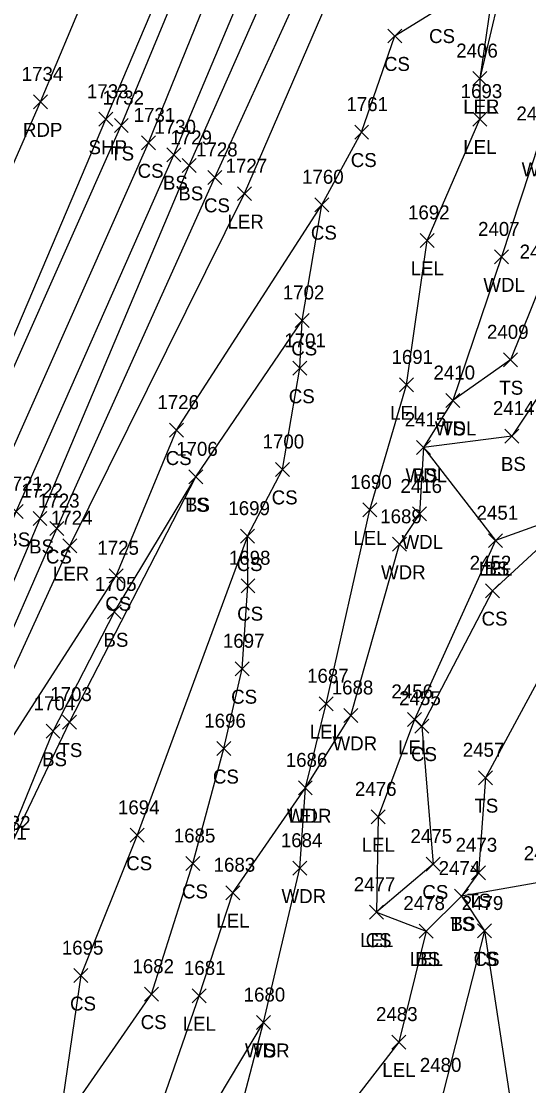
# Model space of a CAD drawing. Extents: x 1483143 to 1488182, y 802902 to 807581.
# Drawn here: x 1487754.7 to 1487827.4, y 806100.3 to 806252.6 of the extents above; entities that cross this region are included whole.
import ezdxf

# ---------------------------------------------------------------- set-up
doc = ezdxf.new("R2010")
doc.units = 0
for name, color, linetype in [('L_A', 7, 'Continuous'), ('L_I', 7, 'Continuous'), ('L_TIC', 7, 'Continuous'), ('LARO', 7, 'Continuous'), ('LAWA', 7, 'Continuous'), ('LELB', 7, 'Continuous'), ('P_A', 7, 'Continuous'), ('P_I', 7, 'Continuous'), ('P_TIC', 7, 'Continuous'), ('PET', 7, 'Continuous'), ('PSP', 7, 'Continuous')]:
    doc.layers.add(name, color=color, linetype=linetype)

msp = doc.modelspace()

# ---------------------------------------------------------------- linework, layer by layer
at = {"layer": 'L_TIC'}
for points in [[(1487807.19, 806249.46), (1487809.19, 806251.46)], [(1487809.19, 806249.46), (1487807.19, 806251.46)], [(1487819.37, 806243.37), (1487821.37, 806245.37)], [(1487821.37, 806243.37), (1487819.37, 806245.37)], [(1487819.37, 806243.37), (1487821.37, 806245.37)], [(1487821.37, 806243.37), (1487819.37, 806245.37)], [(1487819.35, 806237.57), (1487821.35, 806239.57)], [(1487821.35, 806237.57), (1487819.35, 806239.57)], [(1487768.04, 806236.65), (1487770.04, 806238.65)], [(1487770.04, 806236.65), (1487768.04, 806238.65)], [(1487802.44, 806235.71), (1487804.44, 806237.71)], [(1487804.44, 806235.71), (1487802.44, 806237.71)], [(1487771.93, 806234.17), (1487773.93, 806236.17)], [(1487773.93, 806234.17), (1487771.93, 806236.17)], [(1487775.55, 806232.47), (1487777.55, 806234.47)], [(1487777.55, 806232.47), (1487775.55, 806234.47)], [(1487777.76, 806230.94), (1487779.76, 806232.94)], [(1487779.76, 806230.94), (1487777.76, 806232.94)], [(1487781.43, 806229.23), (1487783.43, 806231.23)], [(1487783.43, 806229.23), (1487781.43, 806231.23)], [(1487785.65, 806226.9), (1487787.65, 806228.9)], [(1487787.65, 806226.9), (1487785.65, 806228.9)], [(1487796.73, 806225.32), (1487798.73, 806227.32)], [(1487798.73, 806225.32), (1487796.73, 806227.32)], [(1487796.73, 806225.32), (1487798.73, 806227.32)], [(1487798.73, 806225.32), (1487796.73, 806227.32)], [(1487811.82, 806220.22), (1487813.82, 806222.22)], [(1487813.82, 806220.22), (1487811.82, 806222.22)], [(1487822.44, 806217.85), (1487824.44, 806219.85)], [(1487824.44, 806217.85), (1487822.44, 806219.85)], [(1487793.92, 806208.76), (1487795.92, 806210.76)], [(1487795.92, 806208.76), (1487793.92, 806210.76)], [(1487823.73, 806203.13), (1487825.73, 806205.13)], [(1487825.73, 806203.13), (1487823.73, 806205.13)], [(1487793.57, 806201.91), (1487795.57, 806203.91)], [(1487795.57, 806201.91), (1487793.57, 806203.91)], [(1487808.88, 806199.54), (1487810.88, 806201.54)], [(1487810.88, 806199.54), (1487808.88, 806201.54)], [(1487815.5, 806197.3), (1487817.5, 806199.3)], [(1487817.5, 806197.3), (1487815.5, 806199.3)], [(1487815.5, 806197.3), (1487817.5, 806199.3)], [(1487817.5, 806197.3), (1487815.5, 806199.3)], [(1487775.95, 806193.07), (1487777.95, 806195.07)], [(1487777.95, 806193.07), (1487775.95, 806195.07)], [(1487823.92, 806192.22), (1487825.92, 806194.22)], [(1487825.92, 806192.22), (1487823.92, 806194.22)], [(1487811.31, 806190.59), (1487813.31, 806192.59)], [(1487813.31, 806190.59), (1487811.31, 806192.59)], [(1487811.31, 806190.59), (1487813.31, 806192.59)], [(1487813.31, 806190.59), (1487811.31, 806192.59)], [(1487791.12, 806187.44), (1487793.12, 806189.44)], [(1487793.12, 806187.44), (1487791.12, 806189.44)], [(1487778.72, 806186.39), (1487780.72, 806188.39)], [(1487780.72, 806186.39), (1487778.72, 806188.39)], [(1487778.72, 806186.39), (1487780.72, 806188.39)], [(1487780.72, 806186.39), (1487778.72, 806188.39)], [(1487753, 806181.42), (1487755, 806183.42)], [(1487755, 806181.42), (1487753, 806183.42)], [(1487803.62, 806181.65), (1487805.62, 806183.65)], [(1487805.62, 806181.65), (1487803.62, 806183.65)], [(1487810.73, 806181.07), (1487812.73, 806183.07)], [(1487812.73, 806181.07), (1487810.73, 806183.07)], [(1487756.4, 806180.42), (1487758.4, 806182.42)], [(1487758.4, 806180.42), (1487756.4, 806182.42)], [(1487758.8, 806178.98), (1487760.8, 806180.98)], [(1487760.8, 806178.98), (1487758.8, 806180.98)], [(1487786.1, 806177.9), (1487788.1, 806179.9)], [(1487788.1, 806177.9), (1487786.1, 806179.9)], [(1487760.66, 806176.53), (1487762.66, 806178.53)], [(1487762.66, 806176.53), (1487760.66, 806178.53)], [(1487807.85, 806176.73), (1487809.85, 806178.73)], [(1487809.85, 806176.73), (1487807.85, 806178.73)], [(1487821.58, 806177.25), (1487823.58, 806179.25)], [(1487823.58, 806177.25), (1487821.58, 806179.25)], [(1487821.58, 806177.25), (1487823.58, 806179.25)], [(1487823.58, 806177.25), (1487821.58, 806179.25)], [(1487767.3, 806172.23), (1487769.3, 806174.23)], [(1487769.3, 806172.23), (1487767.3, 806174.23)], [(1487786.17, 806170.8), (1487788.17, 806172.8)], [(1487788.17, 806170.8), (1487786.17, 806172.8)], [(1487821.16, 806170.09), (1487823.16, 806172.09)], [(1487823.16, 806170.09), (1487821.16, 806172.09)], [(1487767.04, 806167.06), (1487769.04, 806169.06)], [(1487769.04, 806167.06), (1487767.04, 806169.06)], [(1487785.32, 806158.92), (1487787.32, 806160.92)], [(1487787.32, 806158.92), (1487785.32, 806160.92)], [(1487797.38, 806153.92), (1487799.38, 806155.92)], [(1487799.38, 806153.92), (1487797.38, 806155.92)], [(1487800.9, 806152.24), (1487802.9, 806154.24)], [(1487802.9, 806152.24), (1487800.9, 806154.24)], [(1487760.63, 806151.29), (1487762.63, 806153.29)], [(1487762.63, 806151.29), (1487760.63, 806153.29)], [(1487810.01, 806151.68), (1487812.01, 806153.68)], [(1487812.01, 806151.68), (1487810.01, 806153.68)], [(1487811.07, 806150.71), (1487813.07, 806152.71)], [(1487813.07, 806150.71), (1487811.07, 806152.71)], [(1487758.26, 806149.98), (1487760.26, 806151.98)], [(1487760.26, 806149.98), (1487758.26, 806151.98)], [(1487782.71, 806147.49), (1487784.71, 806149.49)], [(1487784.71, 806147.49), (1487782.71, 806149.49)], [(1487820.17, 806143.33), (1487822.17, 806145.33)], [(1487822.17, 806143.33), (1487820.17, 806145.33)], [(1487794.38, 806141.88), (1487796.38, 806143.88)], [(1487796.38, 806141.88), (1487794.38, 806143.88)], [(1487794.38, 806141.88), (1487796.38, 806143.88)], [(1487796.38, 806141.88), (1487794.38, 806143.88)], [(1487804.8, 806137.73), (1487806.8, 806139.73)], [(1487806.8, 806137.73), (1487804.8, 806139.73)], [(1487770.3, 806135.09), (1487772.3, 806137.09)], [(1487772.3, 806135.09), (1487770.3, 806137.09)], [(1487778.29, 806131.06), (1487780.29, 806133.06)], [(1487780.29, 806131.06), (1487778.29, 806133.06)], [(1487812.69, 806130.97), (1487814.69, 806132.97)], [(1487814.69, 806130.97), (1487812.69, 806132.97)], [(1487793.61, 806130.39), (1487795.61, 806132.39)], [(1487795.61, 806130.39), (1487793.61, 806132.39)], [(1487819.15, 806129.73), (1487821.15, 806131.73)], [(1487821.15, 806129.73), (1487819.15, 806131.73)], [(1487783.99, 806126.88), (1487785.99, 806128.88)], [(1487785.99, 806126.88), (1487783.99, 806128.88)], [(1487816.72, 806126.4), (1487818.72, 806128.4)], [(1487818.72, 806126.4), (1487816.72, 806128.4)], [(1487816.72, 806126.4), (1487818.72, 806128.4)], [(1487818.72, 806126.4), (1487816.72, 806128.4)], [(1487804.57, 806124.09), (1487806.57, 806126.09)], [(1487806.57, 806124.09), (1487804.57, 806126.09)], [(1487804.57, 806124.09), (1487806.57, 806126.09)], [(1487806.57, 806124.09), (1487804.57, 806126.09)], [(1487811.67, 806121.39), (1487813.67, 806123.39)], [(1487813.67, 806121.39), (1487811.67, 806123.39)], [(1487811.67, 806121.39), (1487813.67, 806123.39)], [(1487813.67, 806121.39), (1487811.67, 806123.39)], [(1487820.03, 806121.4), (1487822.03, 806123.4)], [(1487822.03, 806121.4), (1487820.03, 806123.4)], [(1487820.03, 806121.4), (1487822.03, 806123.4)], [(1487822.03, 806121.4), (1487820.03, 806123.4)], [(1487762.26, 806115.01), (1487764.26, 806117.01)], [(1487764.26, 806115.01), (1487762.26, 806117.01)], [(1487772.37, 806112.36), (1487774.37, 806114.36)], [(1487774.37, 806112.36), (1487772.37, 806114.36)], [(1487779.18, 806112.12), (1487781.18, 806114.12)], [(1487781.18, 806112.12), (1487779.18, 806114.12)], [(1487788.38, 806108.3), (1487790.38, 806110.3)], [(1487790.38, 806108.3), (1487788.38, 806110.3)], [(1487788.38, 806108.3), (1487790.38, 806110.3)], [(1487790.38, 806108.3), (1487788.38, 806110.3)], [(1487807.76, 806105.51), (1487809.76, 806107.51)], [(1487809.76, 806105.51), (1487807.76, 806107.51)]]:
    msp.add_lwpolyline(points, dxfattribs=at)
at = {"layer": 'LARO'}
for points in [[(1487666.95, 805964.97), (1487680.31, 805984.75), (1487702.99, 806037.2), (1487715.7, 806058.03), (1487734.3, 806108.53), (1487742.02, 806134.63), (1487761.66, 806177.53), (1487786.65, 806227.9), (1487808.03, 806277.33), (1487813.76, 806294.17), (1487828.9, 806329), (1487831.91, 806346.68), (1487843.29, 806372.21), (1487845.69, 806380.48), (1487852.63, 806386.9), (1487863.18, 806416.3)], [(1487938.33, 806405.75), (1487927.08, 806402.62), (1487919.67, 806403.09), (1487914.11, 806409.79), (1487906.78, 806399.47), (1487893.33, 806381.44), (1487887.6, 806370.68), (1487880.83, 806355.03), (1487873.24, 806335.95), (1487862.81, 806310.84), (1487845.31, 806291.53), (1487837.06, 806275.13), (1487830.31, 806264.75), (1487822.51, 806259.14), (1487820.37, 806244.37)], [(1487865.1, 806267.91), (1487857.3, 806269.9), (1487840.52, 806269.33), (1487830.31, 806264.75), (1487823.62, 806258.16), (1487820.37, 806244.37)], [(1487820.37, 806244.37), (1487820.35, 806238.57)], [(1487707.45, 805965.6), (1487711.43, 805989.94), (1487729.08, 806015.73), (1487727.61, 806022.94), (1487733.3, 806030.69), (1487757.71, 806067.53), (1487771.86, 806089.23), (1487780.18, 806113.12), (1487784.99, 806127.88), (1487795.38, 806142.88), (1487798.38, 806154.92), (1487804.62, 806182.65), (1487809.88, 806200.54), (1487812.82, 806221.22), (1487820.35, 806238.57)], [(1487840.18, 806185.42), (1487834.67, 806182.6), (1487822.58, 806178.25), (1487811.01, 806152.68), (1487805.8, 806138.73), (1487805.57, 806125.09), (1487812.67, 806122.39), (1487808.76, 806106.51), (1487799.94, 806095.08), (1487791.75, 806069.31), (1487789.16, 806039.67), (1487787.77, 806021.85), (1487782.39, 806010.38), (1487772.44, 806000.5), (1487764.14, 805988.07), (1487767.26, 805965.45), (1487766, 805943.66), (1487763.65, 805933.94), (1487758.69, 805910.3), (1487765.4, 805900.12), (1487775.65, 805902.89)]]:
    msp.add_lwpolyline(points, dxfattribs=at)
at = {"layer": 'LAWA'}
for points in [[(1487942.37, 806424.18), (1487942.13, 806400.96), (1487924.66, 806393.36), (1487906.74, 806373.16), (1487899.59, 806370.18), (1487890.83, 806350.54), (1487893.79, 806329.46), (1487876.29, 806319.09), (1487863.09, 806294.65), (1487840.52, 806269.33), (1487843.55, 806264.22), (1487833.59, 806259.9), (1487830.72, 806250.51), (1487828.92, 806235.37), (1487823.44, 806218.85), (1487816.5, 806198.3), (1487812.31, 806191.59), (1487811.73, 806182.07)], [(1487811.73, 806182.07), (1487808.85, 806177.73)], [(1487715.74, 805966.94), (1487726.15, 805982.46), (1487744.09, 806004.51), (1487749.42, 806025.91), (1487761.62, 806062.94), (1487776.28, 806087.32), (1487789.38, 806109.3), (1487794.61, 806131.39), (1487795.38, 806142.88), (1487801.9, 806153.24), (1487808.85, 806177.73)]]:
    msp.add_lwpolyline(points, dxfattribs=at)
at = {"layer": 'LELB'}
for points in [[(1487406.66, 805485.41), (1487431.45, 805531.24), (1487454.84, 805575.74), (1487473.75, 805612.05), (1487489.43, 805642.37), (1487507.64, 805678.53), (1487524.82, 805711.39), (1487541.86, 805746.09), (1487557.67, 805776.44), (1487575.49, 805812.01), (1487597.52, 805857.93), (1487620.62, 805906.82), (1487641.85, 805951.94), (1487662.18, 805996.35), (1487684.09, 806043.93), (1487694.42, 806066.95), (1487726.58, 806140.7), (1487745.85, 806185.55), (1487769.04, 806237.65), (1487788.58, 806284.85), (1487808.3, 806333.26), (1487827.52, 806379.6), (1487850.09, 806437.73)], [(1487410.04, 805483.24), (1487436.07, 805529.53), (1487459.78, 805575.03), (1487477.42, 805609.67), (1487492.45, 805639.09), (1487509.86, 805677.27), (1487528.68, 805708.85), (1487545.3, 805744.17), (1487561.79, 805774.32), (1487579.7, 805810.21), (1487602.04, 805856.31), (1487624.97, 805905.57), (1487645.72, 805950.02), (1487667.21, 805993.1), (1487687.16, 806043.23), (1487699.2, 806065.16), (1487730.65, 806138.87), (1487749.96, 806183.58), (1487772.93, 806235.17), (1487792.36, 806283.08), (1487812.9, 806331.5), (1487831.61, 806378.23), (1487855.61, 806436.65)], [(1487413.83, 805481.53), (1487440.22, 805526.89), (1487464.36, 805572.85), (1487481.71, 805606.55), (1487496.63, 805636.25), (1487514.9, 805673.97), (1487535.8, 805705.94), (1487549.07, 805741.59), (1487566.17, 805772.22), (1487583.99, 805807.69), (1487605.26, 805855.28), (1487629.33, 805903.01), (1487650.26, 805948.76), (1487670.48, 805991.25), (1487690.28, 806041.74), (1487702.22, 806061.37), (1487704.47, 806066.39), (1487735.28, 806136.71), (1487754, 806182.42), (1487776.55, 806233.47), (1487796.75, 806281.41), (1487816.88, 806330.25), (1487835.19, 806376.59), (1487859.78, 806434.97)], [(1487417, 805480.8), (1487442.28, 805525.8), (1487466.47, 805571.82), (1487483.84, 805604.86), (1487498.25, 805635.76), (1487518.24, 805671.86), (1487538.47, 805704.77), (1487552.2, 805739.67), (1487568.17, 805771.84), (1487585.97, 805806.76), (1487609.39, 805853.47), (1487632.34, 805900.81), (1487653.02, 805947.32), (1487672.59, 805990.01), (1487694.92, 806039.27), (1487707.45, 806059.25), (1487710.05, 806064.3), (1487737.97, 806135.43), (1487757.4, 806181.42), (1487778.76, 806231.94), (1487799.97, 806279.97), (1487818.92, 806329.91), (1487837.5, 806376), (1487863.45, 806433.38)], [(1487539.8, 805706.7), (1487554.99, 805738.51), (1487564.78, 805761.24), (1487572.42, 805770.06), (1487590.42, 805804.18), (1487613.31, 805851.36), (1487639.64, 805896.3), (1487657.07, 805945.9), (1487666.95, 805964.97), (1487675.89, 805987.99), (1487698.82, 806037.9), (1487713.56, 806059.8), (1487740.03, 806134.78), (1487759.8, 806179.98), (1487782.43, 806230.23), (1487804.48, 806278.55), (1487821.45, 806329.34), (1487839.66, 806374.66), (1487865.87, 806433.14)], [(1487757.71, 806067.53), (1487760.04, 806094.14), (1487773.37, 806113.36), (1487779.29, 806132.06), (1487783.71, 806148.49), (1487786.32, 806159.92), (1487787.17, 806171.8), (1487787.1, 806178.9), (1487792.12, 806188.44), (1487794.57, 806202.91), (1487794.92, 806209.76), (1487797.73, 806226.32), (1487803.44, 806236.71), (1487808.19, 806250.46), (1487814.65, 806254.45)], [(1487839.79, 806229.5), (1487829.39, 806215.61), (1487824.73, 806204.13), (1487816.5, 806198.3)], [(1487734.3, 806108.53), (1487743.5, 806131.6), (1487748.42, 806142.35), (1487768.3, 806173.23), (1487776.95, 806194.07), (1487797.73, 806226.32)], [(1487842.83, 806226.01), (1487836.38, 806210.42), (1487824.92, 806193.22), (1487812.31, 806191.59), (1487822.58, 806178.25)], [(1487847.14, 806223.2), (1487840.13, 806209.19), (1487831.79, 806197.78), (1487834.67, 806182.6), (1487832.99, 806166.2), (1487821.17, 806144.33), (1487820.15, 806130.73), (1487817.72, 806127.4), (1487821.03, 806122.4), (1487825.17, 806095.15), (1487826.04, 806071.21), (1487819.68, 806058.95), (1487818.7, 806047.19), (1487815.48, 806048.93), (1487807.41, 806062.56), (1487796.67, 806073.08)], [(1487779.72, 806187.39), (1487794.92, 806209.76)], [(1487709.5, 806045.03), (1487721.98, 806050.95), (1487727.79, 806058.8), (1487736.06, 806080.69), (1487739.04, 806093.16), (1487735.83, 806103.47), (1487734.3, 806108.53), (1487746.67, 806125.92), (1487751.73, 806132.48), (1487759.26, 806150.98), (1487768.04, 806168.06), (1487779.72, 806187.39)], [(1487709.97, 806043.56), (1487721.56, 806049.74), (1487727.77, 806058.21), (1487737.69, 806079.55), (1487741.2, 806090.9), (1487742.36, 806105.05), (1487748.14, 806123.84), (1487752.84, 806133.86), (1487761.63, 806152.29), (1487779.72, 806187.39)], [(1487834.67, 806182.6), (1487822.16, 806171.09), (1487812.07, 806151.71), (1487813.69, 806131.97), (1487805.57, 806125.09)], [(1487787.1, 806178.9), (1487771.3, 806136.09)], [(1487771.3, 806136.09), (1487763.26, 806116.01)], [(1487829.9, 806129.52), (1487817.72, 806127.4), (1487812.67, 806122.39)], [(1487821.03, 806122.4), (1487815.12, 806099.24), (1487803.16, 806087.01), (1487796.67, 806073.08)], [(1487763.26, 806116.01), (1487760.04, 806094.14)], [(1487722.85, 805947.47), (1487728.92, 805957.98), (1487741.86, 805972.44), (1487759.45, 805985.51), (1487774.65, 806014.13), (1487785.01, 806040.02), (1487783.16, 806085.43), (1487789.38, 806109.3)]]:
    msp.add_lwpolyline(points, dxfattribs=at)
at = {"layer": 'P_TIC'}
for points in [[(1487756.48, 806240.03), (1487758.48, 806242.03)], [(1487758.48, 806240.03), (1487756.48, 806242.03)], [(1487765.81, 806237.55), (1487767.81, 806239.55)], [(1487767.81, 806237.55), (1487765.81, 806239.55)]]:
    msp.add_lwpolyline(points, dxfattribs=at)
at = {"layer": 'PET'}
msp.add_lwpolyline([(1487396.33, 805490.41), (1487421.9, 805537.94), (1487444.13, 805580.16), (1487464.29, 805618.83), (1487479.8, 805648.39), (1487498.08, 805684.27), (1487514.57, 805717.15), (1487530.55, 805749.06), (1487547.16, 805782.47), (1487564.33, 805817.54), (1487585.71, 805863.32), (1487608.89, 805911.38), (1487630.35, 805956.68), (1487651.22, 806001.25), (1487672.63, 806048.33), (1487683.65, 806072.29), (1487715.61, 806144.47), (1487735.35, 806190.47), (1487757.48, 806241.03), (1487777.65, 806289.15), (1487798.25, 806337.46), (1487817.05, 806384.04), (1487839.67, 806441.4)], dxfattribs=at)
at = {"layer": 'PSP'}
msp.add_lwpolyline([(1487405.03, 805486.21), (1487429.8, 805532.42), (1487452.92, 805576.31), (1487472.37, 805613.24), (1487487.86, 805643.29), (1487506.35, 805679.4), (1487523.34, 805712.45), (1487540.38, 805746.64), (1487556.03, 805777.85), (1487573.44, 805813.27), (1487595.34, 805859.04), (1487618.37, 805906.67), (1487640.09, 805952.42), (1487660.18, 805997.21), (1487682.38, 806044.71), (1487693.04, 806068.56), (1487725.12, 806141.19), (1487744.39, 806185.87), (1487766.81, 806238.55), (1487786.8, 806285.64), (1487806.77, 806333.93), (1487825.55, 806380.21), (1487847.81, 806437.56)], dxfattribs=at)

# ---------------------------------------------------------------- texts
at = {"layer": 'L_A'}
for s, p in [('CS', (1487813.09, 806249.45)), ('CS', (1487806.63, 806245.46)), ('LER', (1487817.95, 806239.37)), ('LEL', (1487818.01, 806239.37)), ('TS', (1487767.45, 806232.65)), ('LEL', (1487817.98, 806233.57)), ('CS', (1487801.88, 806231.71)), ('CS', (1487771.37, 806230.17)), ('WDL', (1487826.34, 806230.37)), ('BS', (1487774.99, 806228.47)), ('BS', (1487777.2, 806226.94)), ('CS', (1487780.87, 806225.23)), ('LER', (1487784.23, 806222.9)), ('CS', (1487796.17, 806221.32)), ('CS', (1487796.17, 806221.32)), ('LEL', (1487810.46, 806216.22)), ('WDL', (1487820.86, 806213.85)), ('CS', (1487793.36, 806204.76)), ('TS', (1487823.14, 806199.13)), ('CS', (1487793.01, 806197.91)), ('LEL', (1487807.52, 806195.54)), ('WDL', (1487813.92, 806193.3)), ('TS', (1487814.91, 806193.3)), ('CS', (1487775.39, 806189.07)), ('BS', (1487823.37, 806188.22)), ('WDL', (1487809.72, 806186.59)), ('BS', (1487810.75, 806186.59)), ('TS', (1487778.13, 806182.39)), ('BS', (1487778.16, 806182.39)), ('CS', (1487790.56, 806183.44)), ('BS', (1487752.44, 806177.42)), ('BS', (1487755.84, 806176.42)), ('LEL', (1487802.25, 806177.65)), ('WDL', (1487809.15, 806177.07)), ('CS', (1487758.24, 806174.98)), ('CS', (1487785.54, 806173.9)), ('LEL', (1487820.22, 806173.25)), ('BS', (1487821.02, 806173.25)), ('LER', (1487759.24, 806172.53)), ('WDR', (1487806.21, 806172.73)), ('CS', (1487766.74, 806168.23)), ('CS', (1487785.62, 806166.8)), ('CS', (1487820.6, 806166.09)), ('BS', (1487766.48, 806163.06)), ('CS', (1487784.76, 806154.92)), ('LEL', (1487796.01, 806149.92)), ('TS', (1487760.04, 806147.29)), ('WDR', (1487799.27, 806148.24)), ('LEL', (1487808.65, 806147.68)), ('BS', (1487757.7, 806145.98)), ('CS', (1487810.51, 806146.71)), ('CS', (1487782.15, 806143.49)), ('TS', (1487819.58, 806139.33)), ('WDR', (1487792.74, 806137.88)), ('LEL', (1487793.01, 806137.88)), ('LEL', (1487803.44, 806133.73)), ('CS', (1487769.74, 806131.09)), ('CS', (1487777.73, 806127.06)), ('WDR', (1487791.97, 806126.39)), ('CS', (1487812.13, 806126.97)), ('TS', (1487818.56, 806125.73)), ('LEL', (1487782.63, 806122.88)), ('TS', (1487816.13, 806122.4)), ('BS', (1487816.16, 806122.4)), ('LEL', (1487803.21, 806120.09)), ('CS', (1487804.01, 806120.09)), ('LEL', (1487810.31, 806117.39)), ('BS', (1487811.11, 806117.39)), ('TS', (1487819.44, 806117.4)), ('CS', (1487819.47, 806117.4)), ('CS', (1487761.7, 806111.01)), ('CS', (1487771.81, 806108.36)), ('LEL', (1487777.82, 806108.12)), ('WDR', (1487786.74, 806104.3)), ('TS', (1487787.78, 806104.3)), ('LEL', (1487806.39, 806101.51))]:
    msp.add_text(s, height=2, dxfattribs=at).set_placement(p)
at = {"layer": 'L_I'}
for s, p in [('2406', (1487816.98, 806247.37)), ('2406', (1487816.98, 806247.37)), ('1732', (1487766.34, 806240.65)), ('1693', (1487817.61, 806241.57)), ('1761', (1487801.26, 806239.71)), ('1731', (1487770.81, 806238.17)), ('2405', (1487825.59, 806238.37)), ('2405', (1487825.59, 806238.37)), ('1730', (1487773.77, 806236.47)), ('1729', (1487776.06, 806234.94)), ('1728', (1487779.74, 806233.23)), ('1727', (1487783.96, 806230.9)), ('1760', (1487794.91, 806229.32)), ('1760', (1487794.91, 806229.32)), ('1692', (1487810.08, 806224.22)), ('2407', (1487820.1, 806221.85)), ('2408', (1487826.05, 806218.61)), ('1702', (1487792.15, 806212.76)), ('2409', (1487821.38, 806207.13)), ('1701', (1487792.36, 806205.91)), ('1691', (1487807.71, 806203.54)), ('2410', (1487813.72, 806201.3)), ('2410', (1487813.72, 806201.3)), ('1726', (1487774.2, 806197.07)), ('2414', (1487822.23, 806196.22)), ('2415', (1487809.61, 806194.59)), ('2415', (1487809.61, 806194.59)), ('1700', (1487789.26, 806191.44)), ('1706', (1487776.89, 806190.39)), ('1706', (1487776.89, 806190.39)), ('1721', (1487751.88, 806185.42)), ('1690', (1487801.79, 806185.65)), ('1722', (1487754.71, 806184.42)), ('2416', (1487808.99, 806185.07)), ('1723', (1487757.11, 806182.98)), ('1699', (1487784.36, 806181.9)), ('2451', (1487819.89, 806181.25)), ('2451', (1487819.89, 806181.25)), ('1724', (1487758.96, 806180.53)), ('1689', (1487806.1, 806180.73)), ('1725', (1487765.61, 806176.23)), ('1698', (1487784.43, 806174.8)), ('2452', (1487818.9, 806174.09)), ('1705', (1487765.27, 806171.06)), ('1697', (1487783.58, 806162.92)), ('1687', (1487795.63, 806157.92)), ('1703', (1487758.86, 806155.29)), ('1688', (1487799.16, 806156.24)), ('2456', (1487807.7, 806155.68)), ('1704', (1487756.49, 806153.98)), ('2455', (1487808.81, 806154.71)), ('1696', (1487780.91, 806151.49)), ('2457', (1487817.91, 806147.33)), ('1686', (1487792.58, 806145.88)), ('1686', (1487792.58, 806145.88)), ('2476', (1487802.48, 806141.73)), ('1694', (1487768.56, 806139.09)), ('1632', (1487750.1, 806136.86)), ('1631', (1487749.56, 806135.48)), ('1685', (1487776.55, 806135.06)), ('1684', (1487791.87, 806134.39)), ('2475', (1487810.43, 806134.97)), ('2473', (1487816.89, 806133.73)), ('2472', (1487826.64, 806132.52)), ('2472', (1487826.64, 806132.52)), ('1683', (1487782.25, 806130.88)), ('2474', (1487814.46, 806130.4)), ('2474', (1487814.46, 806130.4)), ('2477', (1487802.31, 806128.09)), ('2477', (1487802.31, 806128.09)), ('2478', (1487809.41, 806125.39)), ('2478', (1487809.41, 806125.39)), ('2479', (1487817.76, 806125.4)), ('2479', (1487817.76, 806125.4)), ('1695', (1487760.52, 806119.01)), ('1682', (1487770.63, 806116.36)), ('1681', (1487778, 806116.12)), ('1680', (1487786.55, 806112.3)), ('1680', (1487786.55, 806112.3)), ('2483', (1487805.5, 806109.51)), ('2480', (1487811.77, 806102.24))]:
    msp.add_text(s, height=2, dxfattribs=at).set_placement(p)
at = {"layer": 'P_A'}
for s, p in [('RDP', (1487754.96, 806236.03)), ('SHP', (1487764.35, 806233.55))]:
    msp.add_text(s, height=2, dxfattribs=at).set_placement(p)
at = {"layer": 'P_I'}
for s, p in [('1734', (1487754.78, 806244.03)), ('1733', (1487764.12, 806241.55))]:
    msp.add_text(s, height=2, dxfattribs=at).set_placement(p)

doc.saveas('drawing.dxf')
